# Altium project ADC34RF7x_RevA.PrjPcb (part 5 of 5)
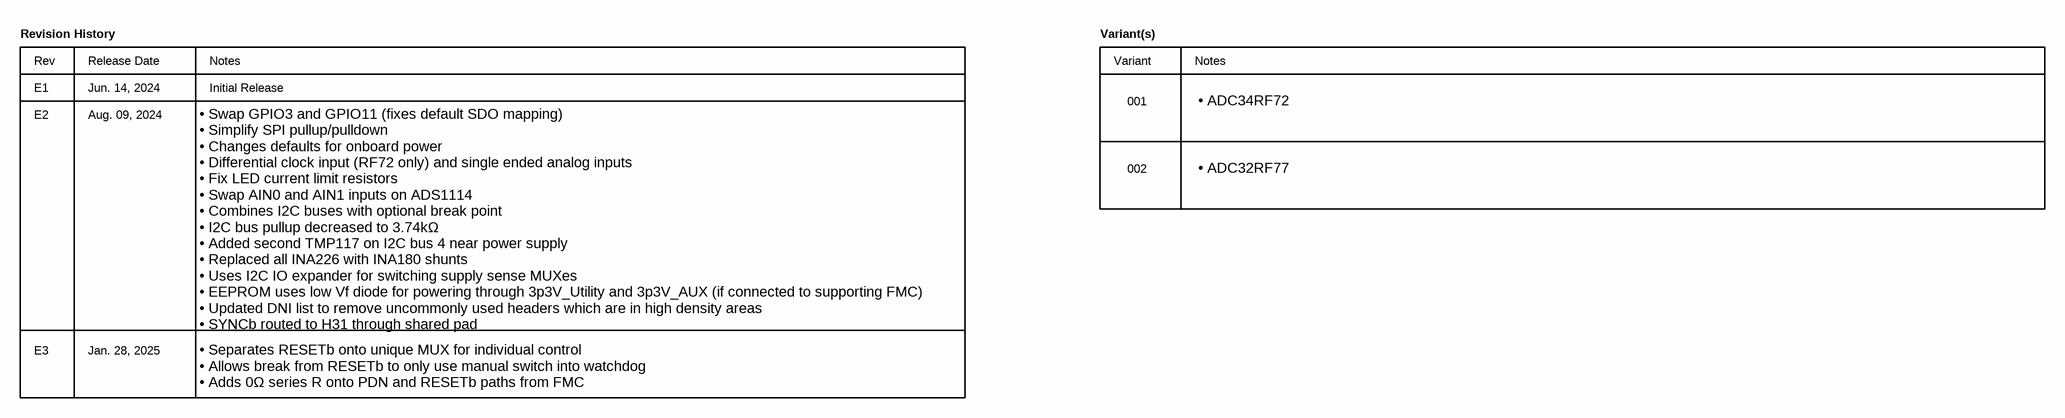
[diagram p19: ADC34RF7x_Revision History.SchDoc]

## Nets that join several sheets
2p3V: ADC34RF7x_Power2_RevA (C221.2 C222.2 FB4.2 FB5.2), ADC34RF7x_Power3_RevA (6 pins), ADC34RF7x_Power4_RevA (6 pins)
3p3V_AUX: ADC34RF7x_FMC_RevA (J29.D32), ADC34RF7x_I2C_Shunts_Margining (D6.1)
3p3V_Utility: ADC34RF7x_LMK_RevA (24 pins), ADC34RF7x_USB_RevA (6 pins), ADC34RF7x_LVL_Shft_RevA (16 pins), ADC34RF7x_MUX_RevA (11 pins), ADC34RF7x_SYSREF_FPGA_MUX_RevA (18 pins), ADC34RF7x_Power1_RevA (C204.2 FC1.3), ADC34RF7x_Power2_RevA (5 pins), ADC34RF7x_Power3_RevA (10 pins), ADC34RF7x_Power4_RevA (10 pins), ADC34RF7x_I2C_Shunts_Margining (51 pins)
12V: ADC34RF7x_Power1_RevA (15 pins), ADC34RF7x_Power_Sequencer (R224.2 R225.1 U62.1), ADC34RF7x_Power2_RevA (16 pins)
AVDD12: ADC34RF7x_ADC_Power_RevA (60 pins), ADC34RF7x_Power3_RevA (C230.2 FB2.2 FB6.2)
AVDD12_I2C_SENSE: ADC34RF7x_I2C_Shunts_Margining (U57.7), ADC34RF7x_uFit_Power (R171.2)
AVDD12_IN: ADC34RF7x_Power3_RevA (C229.2 R133.2 U40.9 U40.10), ADC34RF7x_I2C_Shunts_Margining (R106.1 U33.1)
AVDD12_OUT: ADC34RF7x_Power3_RevA (FB6.1 U40.8), ADC34RF7x_I2C_Shunts_Margining (R106.2 U33.3)
AVDD12_SENSE: ADC34RF7x_ADC_Power_RevA (NT2.1), ADC34RF7x_uFit_Power (R42.1 R171.1)
AVDD12_uFit: ADC34RF7x_Power3_RevA (FB2.1), ADC34RF7x_uFit_Power (J43.11 J43.13)
AVDD18: ADC34RF7x_ADC_Dig_RevA (U3.2), ADC34RF7x_ADC_Power_RevA (38 pins), ADC34RF7x_Power4_RevA (C244.2 FB8.2 FB10.2)
AVDD18_I2C_SENSE: ADC34RF7x_I2C_Shunts_Margining (U57.2), ADC34RF7x_uFit_Power (R174.2)
AVDD18_IN: ADC34RF7x_Power4_RevA (C243.2 R145.2 U46.9 U46.10), ADC34RF7x_I2C_Shunts_Margining (R104.1 U31.1)
AVDD18_OUT: ADC34RF7x_Power4_RevA (FB8.1 U46.8), ADC34RF7x_I2C_Shunts_Margining (R104.2 U31.3)
AVDD18_SENSE: ADC34RF7x_ADC_Power_RevA (NT5.1), ADC34RF7x_uFit_Power (R169.1 R174.1)
AVDD18_uFit: ADC34RF7x_Power4_RevA (FB10.1), ADC34RF7x_uFit_Power (J44.1 J44.3)
CLKVDD12: ADC34RF7x_ADC_Power_RevA (6 pins), ADC34RF7x_Power3_RevA (C237.2 FB3.2 FB7.2)
CLKVDD12_I2C_SENSE: ADC34RF7x_I2C_Shunts_Margining (U57.4), ADC34RF7x_uFit_Power (R172.2)
CLKVDD12_IN: ADC34RF7x_Power3_RevA (C236.2 R139.2 U43.9 U43.10), ADC34RF7x_I2C_Shunts_Margining (R105.1 U32.1)
CLKVDD12_OUT: ADC34RF7x_Power3_RevA (FB7.1 U43.8), ADC34RF7x_I2C_Shunts_Margining (R105.2 U32.3)
CLKVDD12_SENSE: ADC34RF7x_ADC_Power_RevA (NT3.1), ADC34RF7x_uFit_Power (R167.1 R172.1)
CLKVDD12_uFit: ADC34RF7x_Power3_RevA (FB3.1), ADC34RF7x_uFit_Power (J44.9)
CLKVDD18: ADC34RF7x_ADC_Power_RevA (5 pins), ADC34RF7x_Power4_RevA (C251.2 FB9.2 FB11.2)
CLKVDD18_I2C_SENSE: ADC34RF7x_I2C_Shunts_Margining (U57.9), ADC34RF7x_uFit_Power (R173.2)
CLKVDD18_IN: ADC34RF7x_Power4_RevA (C250.2 R151.2 U49.9 U49.10), ADC34RF7x_I2C_Shunts_Margining (R107.1 U34.1)
CLKVDD18_OUT: ADC34RF7x_Power4_RevA (FB9.1 U49.8), ADC34RF7x_I2C_Shunts_Margining (R107.2 U34.3)
CLKVDD18_SENSE: ADC34RF7x_ADC_Power_RevA (NT4.1), ADC34RF7x_uFit_Power (R168.1 R173.1)
CLKVDD18_uFit: ADC34RF7x_Power4_RevA (FB11.1), ADC34RF7x_uFit_Power (J44.13)
DVDD09: ADC34RF7x_ADC_Power_RevA (30 pins), ADC34RF7x_Power2_RevA (7 pins), ADC34RF7x_I2C_Shunts_Margining (R103.2 U28.3)
DVDD09_GND_SENSE: ADC34RF7x_ADC_Power_RevA (NT8.1), ADC34RF7x_uFit_Power (R197.1 R198.1)
DVDD09_I2C_GND_SENSE: ADC34RF7x_I2C_Shunts_Margining (U27.5), ADC34RF7x_uFit_Power (R198.2)
DVDD09_I2C_SENSE: ADC34RF7x_I2C_Shunts_Margining (U27.4), ADC34RF7x_uFit_Power (R170.2)
DVDD09_IN: ADC34RF7x_Power2_RevA (16 pins), ADC34RF7x_I2C_Shunts_Margining (R103.1 U28.1)
DVDD09_SENSE: ADC34RF7x_ADC_Power_RevA (NT1.1), ADC34RF7x_uFit_Power (R41.1 R170.1)
DVDD09_uFit: ADC34RF7x_Power2_RevA (NT6.2 NT7.2), ADC34RF7x_uFit_Power (J43.1 J43.3 J43.5 J43.7)
GND: ADC34RF7x_ADC_Input_AB_RevA (30 pins), ADC34RF7x_ADC_Input_CD_RevA (20 pins), ADC34RF7x_LMK_RevA (28 pins), ADC34RF7x_ADC_Dig_RevA (35 pins), ADC34RF7x_ADC_Power_RevA (129 pins), ADC34RF7x_FMC_RevA (162 pins), ADC34RF7x_USB_RevA (26 pins), ADC34RF7x_LVL_Shft_RevA (28 pins), ADC34RF7x_MUX_RevA (22 pins), ADC34RF7x_SYSREF_FPGA_MUX_RevA (36 pins), ADC34RF7x_Power1_RevA (40 pins), ADC34RF7x_Power_Sequencer (7 pins), ADC34RF7x_Power2_RevA (55 pins), ADC34RF7x_Power3_RevA (24 pins), ADC34RF7x_Power4_RevA (24 pins), ADC34RF7x_I2C_Shunts_Margining (42 pins), ADC34RF7x_uFit_Power (16 pins)
GPIOVDD: ADC34RF7x_ADC_Dig_RevA (R46.1 R47.1 R48.1 U4.6), ADC34RF7x_ADC_Power_RevA (J20.1 U1.L5), ADC34RF7x_LVL_Shft_RevA (8 pins), ADC34RF7x_MUX_RevA (U8.2 U8.6)
VADJ: ADC34RF7x_FMC_RevA (J29.E39 J29.F40 J29.G39 J29.H40), ADC34RF7x_LVL_Shft_RevA (R202.1 SW6.3)
ADC_CLK_N: ADC34RF7x_ADC_Input_AB_RevA (C18.2 C19.2), ADC34RF7x_ADC_Dig_RevA (U1.U9)
ADC_CLK_P: ADC34RF7x_ADC_Input_AB_RevA (C22.2 C23.1), ADC34RF7x_ADC_Dig_RevA (U1.U10)
ADC_JESDCLK_CORECLK_N: ADC34RF7x_FMC_RevA (J29.D9), ADC34RF7x_SYSREF_FPGA_MUX_RevA (U54.10)
ADC_JESDCLK_CORECLK_P: ADC34RF7x_FMC_RevA (J29.D8), ADC34RF7x_SYSREF_FPGA_MUX_RevA (U54.9)
ADC_JESDCLK_N: ADC34RF7x_ADC_Dig_RevA (U1.C9), ADC34RF7x_SYSREF_FPGA_MUX_RevA (C262.2)
ADC_JESDCLK_P: ADC34RF7x_ADC_Dig_RevA (U1.D9), ADC34RF7x_SYSREF_FPGA_MUX_RevA (C261.2)
ADC_JESDCLKIN_LMK_N: ADC34RF7x_LMK_RevA (R55.2), ADC34RF7x_SYSREF_FPGA_MUX_RevA (U56.4)
ADC_JESDCLKIN_LMK_P: ADC34RF7x_LMK_RevA (R54.2), ADC34RF7x_SYSREF_FPGA_MUX_RevA (U56.5)
ADC_JESDCLKIN_N: ADC34RF7x_ADC_Dig_RevA (R180.1 U1.P12), ADC34RF7x_SYSREF_FPGA_MUX_RevA (C68.1)
ADC_JESDCLKIN_P: ADC34RF7x_ADC_Dig_RevA (R180.2 U1.N12), ADC34RF7x_SYSREF_FPGA_MUX_RevA (C65.1)
ADC_SYSREF_LMK_N: ADC34RF7x_LMK_RevA (R61.2), ADC34RF7x_SYSREF_FPGA_MUX_RevA (U55.5)
ADC_SYSREF_LMK_P: ADC34RF7x_LMK_RevA (R58.2), ADC34RF7x_SYSREF_FPGA_MUX_RevA (U55.4)
ADC_SYSREF_N: ADC34RF7x_ADC_Dig_RevA (U1.U6), ADC34RF7x_SYSREF_FPGA_MUX_RevA (R204.2)
ADC_SYSREF_P: ADC34RF7x_ADC_Dig_RevA (U1.U7), ADC34RF7x_SYSREF_FPGA_MUX_RevA (R205.2)
ADC_SYSREFOUT_N: ADC34RF7x_ADC_Dig_RevA (U1.L1), ADC34RF7x_SYSREF_FPGA_MUX_RevA (C260.2)
ADC_SYSREFOUT_P: ADC34RF7x_ADC_Dig_RevA (U1.K1), ADC34RF7x_SYSREF_FPGA_MUX_RevA (C259.2)
CSb_LMK: ADC34RF7x_LMK_RevA (U2.18), ADC34RF7x_MUX_RevA (J21.5 U6.5)
CSb_LMK_FMC_3p3V: ADC34RF7x_LVL_Shft_RevA (U15.11), ADC34RF7x_MUX_RevA (U6.4)
CSb_LMK_FMC_VADJ: ADC34RF7x_FMC_RevA (J29.G16), ADC34RF7x_LVL_Shft_RevA (U15.2 U17.1)
CSb_LMK_USB: ADC34RF7x_USB_RevA (J28.29), ADC34RF7x_MUX_RevA (U6.3)
DCLKA_N: ADC34RF7x_ADC_Dig_RevA (U1.F17), ADC34RF7x_FMC_RevA (J29.D21)
DCLKA_P: ADC34RF7x_ADC_Dig_RevA (U1.E17), ADC34RF7x_FMC_RevA (J29.D20)
DCLKB_N: ADC34RF7x_ADC_Dig_RevA (U1.F1), ADC34RF7x_FMC_RevA (J29.F4)
DCLKB_P: ADC34RF7x_ADC_Dig_RevA (U1.E1), ADC34RF7x_FMC_RevA (J29.F5)
DOUT0_FMC_N: ADC34RF7x_ADC_Dig_RevA (C77.2), ADC34RF7x_FMC_RevA (J29.A18)
DOUT0_FMC_P: ADC34RF7x_ADC_Dig_RevA (C76.2), ADC34RF7x_FMC_RevA (J29.A19)
DOUT1_FMC_N: ADC34RF7x_ADC_Dig_RevA (C79.2), ADC34RF7x_FMC_RevA (J29.B16)
DOUT1_FMC_P: ADC34RF7x_ADC_Dig_RevA (C78.2), ADC34RF7x_FMC_RevA (J29.B17)
DOUT2_FMC_N: ADC34RF7x_ADC_Dig_RevA (C81.2), ADC34RF7x_FMC_RevA (J29.A14)
DOUT2_FMC_P: ADC34RF7x_ADC_Dig_RevA (C80.2), ADC34RF7x_FMC_RevA (J29.A15)
DOUT3_FMC_N: ADC34RF7x_ADC_Dig_RevA (C83.2), ADC34RF7x_FMC_RevA (J29.B12)
DOUT3_FMC_P: ADC34RF7x_ADC_Dig_RevA (C82.2), ADC34RF7x_FMC_RevA (J29.B13)
DOUT4_FMC_N: ADC34RF7x_ADC_Dig_RevA (C85.2), ADC34RF7x_FMC_RevA (J29.A2)
DOUT4_FMC_P: ADC34RF7x_ADC_Dig_RevA (C84.2), ADC34RF7x_FMC_RevA (J29.A3)
DOUT5_FMC_N: ADC34RF7x_ADC_Dig_RevA (C87.2), ADC34RF7x_FMC_RevA (J29.C6)
DOUT5_FMC_P: ADC34RF7x_ADC_Dig_RevA (C86.2), ADC34RF7x_FMC_RevA (J29.C7)
DOUT6_FMC_N: ADC34RF7x_ADC_Dig_RevA (C89.2), ADC34RF7x_FMC_RevA (J29.A6)
DOUT6_FMC_P: ADC34RF7x_ADC_Dig_RevA (C88.2), ADC34RF7x_FMC_RevA (J29.A7)
DOUT7_FMC_N: ADC34RF7x_ADC_Dig_RevA (C91.2), ADC34RF7x_FMC_RevA (J29.A10)
DOUT7_FMC_P: ADC34RF7x_ADC_Dig_RevA (C90.2), ADC34RF7x_FMC_RevA (J29.A11)
FCLKA_N: ADC34RF7x_ADC_Dig_RevA (U1.H17), ADC34RF7x_FMC_RevA (J29.G3)
FCLKA_P: ADC34RF7x_ADC_Dig_RevA (U1.G17), ADC34RF7x_FMC_RevA (J29.G2)
FCLKB_N: ADC34RF7x_ADC_Dig_RevA (U1.H1), ADC34RF7x_FMC_RevA (J29.E2)
FCLKB_P: ADC34RF7x_ADC_Dig_RevA (U1.G1), ADC34RF7x_FMC_RevA (J29.E3)
FMC_GA0: ADC34RF7x_FMC_RevA (J29.C34), ADC34RF7x_I2C_Shunts_Margining (R212.1 U13.1)
FMC_GA1: ADC34RF7x_FMC_RevA (J29.D35), ADC34RF7x_I2C_Shunts_Margining (R213.1 U13.2)
FPGA_SYSREF_LMK_N: ADC34RF7x_LMK_RevA (R181.2), ADC34RF7x_SYSREF_FPGA_MUX_RevA (C101.2)
FPGA_SYSREF_LMK_P: ADC34RF7x_LMK_RevA (R166.2), ADC34RF7x_SYSREF_FPGA_MUX_RevA (C100.2)
FPGA_SYSREF_N: ADC34RF7x_FMC_RevA (J29.G10), ADC34RF7x_SYSREF_FPGA_MUX_RevA (U53.12)
FPGA_SYSREF_P: ADC34RF7x_FMC_RevA (J29.G9), ADC34RF7x_SYSREF_FPGA_MUX_RevA (U53.11)
GPIO0_ADC: ADC34RF7x_ADC_Dig_RevA (J13.1 U1.J4), ADC34RF7x_MUX_RevA (U10.12)
GPIO1_ADC: ADC34RF7x_ADC_Dig_RevA (J13.3 U1.K4), ADC34RF7x_MUX_RevA (U10.1)
GPIO2_ADC: ADC34RF7x_ADC_Dig_RevA (J13.5 U1.L14), ADC34RF7x_MUX_RevA (U10.14)
GPIO3_ADC: ADC34RF7x_ADC_Dig_RevA (J13.7 U1.J15), ADC34RF7x_MUX_RevA (U10.5)
GPIO8_ADC: ADC34RF7x_ADC_Dig_RevA (J41.1 U1.L4), ADC34RF7x_MUX_RevA (U10.15)
GPIO9_ADC: ADC34RF7x_ADC_Dig_RevA (J41.3 U1.J3), ADC34RF7x_MUX_RevA (U10.11)
GPIO10_ADC: ADC34RF7x_ADC_Dig_RevA (J41.5 U1.K3), ADC34RF7x_MUX_RevA (U10.2)
GPIO13_ADC: ADC34RF7x_ADC_Dig_RevA (J41.11 U1.K2), ADC34RF7x_MUX_RevA (U10.4)
GPIO14_ADC: ADC34RF7x_ADC_Dig_RevA (J41.13 U1.L2), ADC34RF7x_LVL_Shft_RevA (U24.10)
GPIO14_FPGA: ADC34RF7x_FMC_RevA (J29.H19), ADC34RF7x_LVL_Shft_RevA (U24.3)
GPIO15_ADC: ADC34RF7x_ADC_Dig_RevA (J41.15 U1.C2), ADC34RF7x_LVL_Shft_RevA (U24.9)
GPIO15_FPGA: ADC34RF7x_FMC_RevA (J29.H20), ADC34RF7x_LVL_Shft_RevA (U24.4)
GPIO16_ADC: ADC34RF7x_ADC_Dig_RevA (J42.1 U1.D2), ADC34RF7x_LVL_Shft_RevA (U22.12)
GPIO16_FPGA: ADC34RF7x_FMC_RevA (J29.J18), ADC34RF7x_LVL_Shft_RevA (U22.1)
GPIO17_ADC: ADC34RF7x_ADC_Dig_RevA (J42.3 U1.K16), ADC34RF7x_LVL_Shft_RevA (U22.11)
GPIO17_FPGA: ADC34RF7x_FMC_RevA (J29.J19), ADC34RF7x_LVL_Shft_RevA (U22.2)
GPIO18_ADC: ADC34RF7x_ADC_Dig_RevA (J42.5 U1.L16), ADC34RF7x_LVL_Shft_RevA (U22.10)
GPIO18_FPGA: ADC34RF7x_FMC_RevA (J29.J21), ADC34RF7x_LVL_Shft_RevA (U22.3)
GPIO19_ADC: ADC34RF7x_ADC_Dig_RevA (J42.7 U1.J17), ADC34RF7x_LVL_Shft_RevA (U22.9)
GPIO19_FPGA: ADC34RF7x_FMC_RevA (J29.J22), ADC34RF7x_LVL_Shft_RevA (U22.4)
GPIO20_ADC: ADC34RF7x_ADC_Dig_RevA (J42.9 U1.K17), ADC34RF7x_LVL_Shft_RevA (U25.12)
GPIO20_FPGA: ADC34RF7x_FMC_RevA (J29.K19), ADC34RF7x_LVL_Shft_RevA (U25.1)
GPIO21_ADC: ADC34RF7x_ADC_Dig_RevA (J42.11 U1.L17), ADC34RF7x_LVL_Shft_RevA (U25.11)
GPIO21_FPGA: ADC34RF7x_FMC_RevA (J29.K20), ADC34RF7x_LVL_Shft_RevA (U25.2)
GPIO22_ADC: ADC34RF7x_ADC_Dig_RevA (J42.13 U1.C16), ADC34RF7x_LVL_Shft_RevA (U25.10)
GPIO22_FPGA: ADC34RF7x_FMC_RevA (J29.K22), ADC34RF7x_LVL_Shft_RevA (U25.3)
GPIO23_ADC: ADC34RF7x_ADC_Dig_RevA (J42.15 U1.D16), ADC34RF7x_LVL_Shft_RevA (U25.9)
GPIO23_FPGA: ADC34RF7x_FMC_RevA (J29.K23), ADC34RF7x_LVL_Shft_RevA (U25.4)
GPIO_MUX0_FT: ADC34RF7x_USB_RevA (J28.9), ADC34RF7x_LVL_Shft_RevA (U19.3)
GPIO_MUX1_FT: ADC34RF7x_USB_RevA (J28.11), ADC34RF7x_LVL_Shft_RevA (U19.4)
GPIO_MUX_0_FMC_GPIOVDD: ADC34RF7x_LVL_Shft_RevA (U24.12), ADC34RF7x_MUX_RevA (U11.1)
GPIO_MUX_0_FPGA: ADC34RF7x_FMC_RevA (R200.1 R201.2), ADC34RF7x_LVL_Shft_RevA (U24.1)
GPIO_MUX_0_USB_GPIOVDD: ADC34RF7x_LVL_Shft_RevA (U19.10), ADC34RF7x_MUX_RevA (U11.16)
GPIO_MUX_1_FMC_GPIOVDD: ADC34RF7x_LVL_Shft_RevA (U24.11), ADC34RF7x_MUX_RevA (U11.4)
GPIO_MUX_1_FPGA: ADC34RF7x_FMC_RevA (J29.H17), ADC34RF7x_LVL_Shft_RevA (U24.2)
GPIO_MUX_1_USB_GPIOVDD: ADC34RF7x_LVL_Shft_RevA (U19.9), ADC34RF7x_MUX_RevA (U11.3)
INA_ADC_N: ADC34RF7x_ADC_Input_AB_RevA (R2.2 R4.2), ADC34RF7x_ADC_Dig_RevA (U1.R17)
INA_ADC_P: ADC34RF7x_ADC_Input_AB_RevA (R4.1 R7.2), ADC34RF7x_ADC_Dig_RevA (U1.P17)
INB_ADC_N: ADC34RF7x_ADC_Input_AB_RevA (R9.2 R11.2), ADC34RF7x_ADC_Dig_RevA (U1.U14)
INB_ADC_P: ADC34RF7x_ADC_Input_AB_RevA (R11.1 R14.2), ADC34RF7x_ADC_Dig_RevA (U1.U15)
INC_ADC_N: ADC34RF7x_ADC_Input_CD_RevA (R20.2 R22.2), ADC34RF7x_ADC_Dig_RevA (U1.P1)
INC_ADC_P: ADC34RF7x_ADC_Input_CD_RevA (R22.1 R25.2), ADC34RF7x_ADC_Dig_RevA (U1.R1)
IND_ADC_N: ADC34RF7x_ADC_Input_CD_RevA (R27.2 R29.2), ADC34RF7x_ADC_Dig_RevA (U1.U3)
IND_ADC_P: ADC34RF7x_ADC_Input_CD_RevA (R29.1 R32.2), ADC34RF7x_ADC_Dig_RevA (U1.U4)
LMK_CLK: ADC34RF7x_ADC_Input_AB_RevA (R18.1), ADC34RF7x_LMK_RevA (C55.1)
LMK_CORECLK_N: ADC34RF7x_LMK_RevA (R81.2), ADC34RF7x_FMC_RevA (J29.G7)
LMK_CORECLK_P: ADC34RF7x_LMK_RevA (R80.2), ADC34RF7x_FMC_RevA (J29.G6)
LVDSA0_N: ADC34RF7x_ADC_Dig_RevA (U1.G11), ADC34RF7x_FMC_RevA (J29.C23)
LVDSA0_P: ADC34RF7x_ADC_Dig_RevA (U1.H11), ADC34RF7x_FMC_RevA (J29.C22)
LVDSA1_N: ADC34RF7x_ADC_Dig_RevA (U1.E11), ADC34RF7x_FMC_RevA (J29.D24)
LVDSA1_P: ADC34RF7x_ADC_Dig_RevA (U1.F11), ADC34RF7x_FMC_RevA (J29.D23)
LVDSA2_N: ADC34RF7x_ADC_Dig_RevA (U1.C11), ADC34RF7x_FMC_RevA (J29.G22)
LVDSA2_P: ADC34RF7x_ADC_Dig_RevA (U1.D11), ADC34RF7x_FMC_RevA (J29.G21)
LVDSA3_N: ADC34RF7x_ADC_Dig_RevA (U1.G12), ADC34RF7x_FMC_RevA (J29.H23)
LVDSA3_P: ADC34RF7x_ADC_Dig_RevA (U1.H12), ADC34RF7x_FMC_RevA (J29.H22)
LVDSA4_N: ADC34RF7x_ADC_Dig_RevA (U1.E12), ADC34RF7x_FMC_RevA (J29.D27)
LVDSA4_P: ADC34RF7x_ADC_Dig_RevA (U1.F12), ADC34RF7x_FMC_RevA (J29.D26)
LVDSA5_N: ADC34RF7x_ADC_Dig_RevA (U1.C12), ADC34RF7x_FMC_RevA (J29.C27)
LVDSA5_P: ADC34RF7x_ADC_Dig_RevA (U1.D12), ADC34RF7x_FMC_RevA (J29.C26)
LVDSA6_N: ADC34RF7x_ADC_Dig_RevA (U1.E13), ADC34RF7x_FMC_RevA (J29.H25)
LVDSA6_P: ADC34RF7x_ADC_Dig_RevA (U1.F13), ADC34RF7x_FMC_RevA (J29.H26)
LVDSA7_N: ADC34RF7x_ADC_Dig_RevA (U1.C13), ADC34RF7x_FMC_RevA (J29.G25)
LVDSA7_P: ADC34RF7x_ADC_Dig_RevA (U1.D13), ADC34RF7x_FMC_RevA (J29.G24)
LVDSA8_N: ADC34RF7x_ADC_Dig_RevA (U1.G14), ADC34RF7x_FMC_RevA (J29.H37)
LVDSA8_P: ADC34RF7x_ADC_Dig_RevA (U1.H14), ADC34RF7x_FMC_RevA (J29.H38)
LVDSA9_N: ADC34RF7x_ADC_Dig_RevA (U1.E14), ADC34RF7x_FMC_RevA (J29.H29)
LVDSA9_P: ADC34RF7x_ADC_Dig_RevA (U1.F14), ADC34RF7x_FMC_RevA (J29.H28)
LVDSA10_N: ADC34RF7x_ADC_Dig_RevA (U1.C14), ADC34RF7x_FMC_RevA (J29.G28)
LVDSA10_P: ADC34RF7x_ADC_Dig_RevA (U1.D14), ADC34RF7x_FMC_RevA (J29.G27)
LVDSA11_N: ADC34RF7x_ADC_Dig_RevA (U1.G15), ADC34RF7x_FMC_RevA (J29.G36)
LVDSA11_P: ADC34RF7x_ADC_Dig_RevA (U1.H15), ADC34RF7x_FMC_RevA (J29.G37)
LVDSA12_N: ADC34RF7x_ADC_Dig_RevA (U1.E15), ADC34RF7x_FMC_RevA (R183.2)
LVDSA12_P: ADC34RF7x_ADC_Dig_RevA (U1.F15), ADC34RF7x_FMC_RevA (R184.2)
LVDSA13_N: ADC34RF7x_ADC_Dig_RevA (U1.C15), ADC34RF7x_FMC_RevA (J29.G30)
LVDSA13_P: ADC34RF7x_ADC_Dig_RevA (U1.D15), ADC34RF7x_FMC_RevA (J29.G31)
LVDSA14_N: ADC34RF7x_ADC_Dig_RevA (U1.G16), ADC34RF7x_FMC_RevA (J29.H34)
LVDSA14_P: ADC34RF7x_ADC_Dig_RevA (U1.H16), ADC34RF7x_FMC_RevA (J29.H35)
LVDSA15_N: ADC34RF7x_ADC_Dig_RevA (U1.E16), ADC34RF7x_FMC_RevA (J29.G33)
LVDSA15_P: ADC34RF7x_ADC_Dig_RevA (U1.F16), ADC34RF7x_FMC_RevA (J29.G34)
LVDSB0_N: ADC34RF7x_ADC_Dig_RevA (U1.G7), ADC34RF7x_FMC_RevA (J29.E13)
LVDSB0_P: ADC34RF7x_ADC_Dig_RevA (U1.H7), ADC34RF7x_FMC_RevA (J29.E12)
LVDSB1_N: ADC34RF7x_ADC_Dig_RevA (U1.E7), ADC34RF7x_FMC_RevA (J29.K16)
LVDSB1_P: ADC34RF7x_ADC_Dig_RevA (U1.F7), ADC34RF7x_FMC_RevA (J29.K17)
LVDSB2_N: ADC34RF7x_ADC_Dig_RevA (U1.C7), ADC34RF7x_FMC_RevA (J29.F16)
LVDSB2_P: ADC34RF7x_ADC_Dig_RevA (U1.D7), ADC34RF7x_FMC_RevA (J29.F17)
LVDSB3_N: ADC34RF7x_ADC_Dig_RevA (U1.G6), ADC34RF7x_FMC_RevA (J29.E7)
LVDSB3_P: ADC34RF7x_ADC_Dig_RevA (U1.H6), ADC34RF7x_FMC_RevA (J29.E6)
LVDSB4_N: ADC34RF7x_ADC_Dig_RevA (U1.E6), ADC34RF7x_FMC_RevA (J29.E10)
LVDSB4_P: ADC34RF7x_ADC_Dig_RevA (U1.F6), ADC34RF7x_FMC_RevA (J29.E9)
LVDSB5_N: ADC34RF7x_ADC_Dig_RevA (U1.C6), ADC34RF7x_FMC_RevA (J29.E16)
LVDSB5_P: ADC34RF7x_ADC_Dig_RevA (U1.D6), ADC34RF7x_FMC_RevA (J29.E15)
LVDSB6_N: ADC34RF7x_ADC_Dig_RevA (U1.E5), ADC34RF7x_FMC_RevA (J29.J16)
LVDSB6_P: ADC34RF7x_ADC_Dig_RevA (U1.F5), ADC34RF7x_FMC_RevA (J29.J15)
LVDSB7_N: ADC34RF7x_ADC_Dig_RevA (U1.C5), ADC34RF7x_FMC_RevA (J29.K11)
LVDSB7_P: ADC34RF7x_ADC_Dig_RevA (U1.D5), ADC34RF7x_FMC_RevA (J29.K10)
LVDSB8_N: ADC34RF7x_ADC_Dig_RevA (U1.G4), ADC34RF7x_FMC_RevA (J29.F11)
LVDSB8_P: ADC34RF7x_ADC_Dig_RevA (U1.H4), ADC34RF7x_FMC_RevA (J29.F10)
LVDSB9_N: ADC34RF7x_ADC_Dig_RevA (U1.E4), ADC34RF7x_FMC_RevA (J29.F8)
LVDSB9_P: ADC34RF7x_ADC_Dig_RevA (U1.F4), ADC34RF7x_FMC_RevA (J29.F7)
LVDSB10_N: ADC34RF7x_ADC_Dig_RevA (U1.C4), ADC34RF7x_FMC_RevA (J29.F14)
LVDSB10_P: ADC34RF7x_ADC_Dig_RevA (U1.D4), ADC34RF7x_FMC_RevA (J29.F13)
LVDSB11_N: ADC34RF7x_ADC_Dig_RevA (U1.G3), ADC34RF7x_FMC_RevA (J29.K8)
LVDSB11_P: ADC34RF7x_ADC_Dig_RevA (U1.H3), ADC34RF7x_FMC_RevA (J29.K7)
LVDSB12_N: ADC34RF7x_ADC_Dig_RevA (U1.E3), ADC34RF7x_FMC_RevA (J29.K14)
LVDSB12_P: ADC34RF7x_ADC_Dig_RevA (U1.F3), ADC34RF7x_FMC_RevA (J29.K13)
LVDSB13_N: ADC34RF7x_ADC_Dig_RevA (U1.C3), ADC34RF7x_FMC_RevA (J29.J10)
LVDSB13_P: ADC34RF7x_ADC_Dig_RevA (U1.D3), ADC34RF7x_FMC_RevA (J29.J9)
LVDSB14_N: ADC34RF7x_ADC_Dig_RevA (U1.G2), ADC34RF7x_FMC_RevA (J29.J7)
LVDSB14_P: ADC34RF7x_ADC_Dig_RevA (U1.H2), ADC34RF7x_FMC_RevA (J29.J6)
LVDSB15_N: ADC34RF7x_ADC_Dig_RevA (U1.E2), ADC34RF7x_FMC_RevA (J29.J12)
LVDSB15_P: ADC34RF7x_ADC_Dig_RevA (U1.F2), ADC34RF7x_FMC_RevA (J29.J13)
MGTREFCLK0_FMC_N: ADC34RF7x_FMC_RevA (J29.D5), ADC34RF7x_SYSREF_FPGA_MUX_RevA (C64.1)
MGTREFCLK0_FMC_P: ADC34RF7x_FMC_RevA (J29.D4), ADC34RF7x_SYSREF_FPGA_MUX_RevA (C59.1)
MGTREFCLK0_LMK_N: ADC34RF7x_LMK_RevA (R63.2), ADC34RF7x_SYSREF_FPGA_MUX_RevA (U52.4)
MGTREFCLK0_LMK_P: ADC34RF7x_LMK_RevA (R62.2), ADC34RF7x_SYSREF_FPGA_MUX_RevA (U52.5)
MGTREFCLK1_FMC_N: ADC34RF7x_LMK_RevA (C67.2), ADC34RF7x_FMC_RevA (J29.B21)
MGTREFCLK1_FMC_P: ADC34RF7x_LMK_RevA (C66.2), ADC34RF7x_FMC_RevA (J29.B20)
PDN_ADC_FMC_GPIOVDD: ADC34RF7x_LVL_Shft_RevA (U21.6), ADC34RF7x_MUX_RevA (U11.11)
PDN_ADC_FMC_VADJ: ADC34RF7x_FMC_RevA (R218.1), ADC34RF7x_LVL_Shft_RevA (R238.1 U21.3)
PDN_ADC_FT: ADC34RF7x_USB_RevA (J28.5), ADC34RF7x_LVL_Shft_RevA (U19.2)
PDN_ADC_GPIOVDD: ADC34RF7x_ADC_Dig_RevA (J41.9 R50.1 U1.J2), ADC34RF7x_MUX_RevA (U11.10)
PDN_ADC_USB_GPIOVDD: ADC34RF7x_LVL_Shft_RevA (U19.11), ADC34RF7x_MUX_RevA (U11.12)
PG-3p3V_Util: ADC34RF7x_Power1_RevA (R112.1 U36.19), ADC34RF7x_Power2_RevA (R228.1 U64.2)
PG-M2C: ADC34RF7x_FMC_RevA (D2.1 R199.1), ADC34RF7x_Power4_RevA (R233.2)
PG-switcher: ADC34RF7x_Power2_RevA (R125.2 U39.3), ADC34RF7x_Power3_RevA (R232.1 U66.2)
PG-VDD12: ADC34RF7x_Power3_RevA (R229.2), ADC34RF7x_Power4_RevA (R235.1 U68.1)
RSTb_ADC_FMC_GPIOVDD: ADC34RF7x_LVL_Shft_RevA (U21.7), ADC34RF7x_MUX_RevA (U61.4)
RSTb_ADC_FMC_VADJ: ADC34RF7x_FMC_RevA (R217.1), ADC34RF7x_LVL_Shft_RevA (R237.1 U21.2)
RSTb_ADC_FT: ADC34RF7x_USB_RevA (J28.3), ADC34RF7x_LVL_Shft_RevA (U19.1)
RSTb_ADC_GPIOVDD: ADC34RF7x_ADC_Dig_RevA (R219.1), ADC34RF7x_MUX_RevA (U61.1)
RSTb_ADC_USB_GPIOVDD: ADC34RF7x_LVL_Shft_RevA (U19.12), ADC34RF7x_MUX_RevA (U61.5)
SCL: ADC34RF7x_USB_RevA (R66.1 R68.1 R69.1 TP6.1), ADC34RF7x_I2C_Shunts_Margining (6 pins)
SCL0: ADC34RF7x_Power3_RevA (U44.3 U45.3), ADC34RF7x_I2C_Shunts_Margining (R93.1 U26.2)
SCL1: ADC34RF7x_Power4_RevA (U50.3 U51.3), ADC34RF7x_I2C_Shunts_Margining (R95.1 U26.4)
SCL2: ADC34RF7x_Power2_RevA (U38.3), ADC34RF7x_I2C_Shunts_Margining (R97.1 U26.6)
SCL3: ADC34RF7x_Power4_RevA (U47.3 U48.3), ADC34RF7x_I2C_Shunts_Margining (R99.1 U26.8)
SCL4: ADC34RF7x_Power3_RevA (U41.3 U42.3), ADC34RF7x_I2C_Shunts_Margining (R101.1 U26.11 U60.A2)
SCL_FMC: ADC34RF7x_FMC_RevA (J29.C30), ADC34RF7x_LVL_Shft_RevA (U9.6)
SCL_FMC_3p3V: ADC34RF7x_USB_RevA (R69.2), ADC34RF7x_LVL_Shft_RevA (U9.3)
SCLK_ADC: ADC34RF7x_ADC_Dig_RevA (J13.11 U1.K15), ADC34RF7x_MUX_RevA (R59.2)
SCLK_ADC_FMC_GPIOVDD: ADC34RF7x_LVL_Shft_RevA (U18.12), ADC34RF7x_MUX_RevA (U7.1)
SCLK_ADC_FT: ADC34RF7x_USB_RevA (J28.4), ADC34RF7x_LVL_Shft_RevA (U23.1)
SCLK_ADC_USB_GPIOVDD: ADC34RF7x_LVL_Shft_RevA (U23.12), ADC34RF7x_MUX_RevA (U7.16)
SCLK_FMC_VADJ: ADC34RF7x_FMC_RevA (J29.G12), ADC34RF7x_LVL_Shft_RevA (U15.1 U18.1)
SCLK_FPGA_FT: ADC34RF7x_USB_RevA (J28.40), ADC34RF7x_LVL_Shft_RevA (U16.1)
SCLK_FPGA_VADJ: ADC34RF7x_FMC_RevA (J29.C10), ADC34RF7x_LVL_Shft_RevA (U16.12)
SCLK_LMK: ADC34RF7x_LMK_RevA (U2.19), ADC34RF7x_MUX_RevA (R53.1)
SCLK_LMK_FMC_3p3V: ADC34RF7x_LVL_Shft_RevA (U15.12), ADC34RF7x_MUX_RevA (U6.1)
SCLK_LMK_USB: ADC34RF7x_USB_RevA (J28.33), ADC34RF7x_MUX_RevA (U6.16)
SDA: ADC34RF7x_USB_RevA (R67.1 R185.1 R186.1 TP7.1), ADC34RF7x_I2C_Shunts_Margining (6 pins)
SDA0: ADC34RF7x_Power3_RevA (U44.4 U45.4), ADC34RF7x_I2C_Shunts_Margining (R92.1 U26.1)
SDA1: ADC34RF7x_Power4_RevA (U50.4 U51.4), ADC34RF7x_I2C_Shunts_Margining (R94.1 U26.3)
SDA2: ADC34RF7x_Power2_RevA (U38.4), ADC34RF7x_I2C_Shunts_Margining (R96.1 U26.5)
SDA3: ADC34RF7x_Power4_RevA (U47.4 U48.4), ADC34RF7x_I2C_Shunts_Margining (R98.1 U26.7)
SDA4: ADC34RF7x_Power3_RevA (U41.4 U42.4), ADC34RF7x_I2C_Shunts_Margining (R100.1 U26.10 U60.A1)
SDA_FMC: ADC34RF7x_FMC_RevA (J29.C31), ADC34RF7x_LVL_Shft_RevA (U9.7)
SDA_FMC_3p3V: ADC34RF7x_USB_RevA (R186.2), ADC34RF7x_LVL_Shft_RevA (U9.2)
SDI_FMC_VADJ: ADC34RF7x_FMC_RevA (J29.G13), ADC34RF7x_LVL_Shft_RevA (U15.3 U18.3)
SDI_LMK_USB: ADC34RF7x_USB_RevA (J28.35), ADC34RF7x_MUX_RevA (U6.9)
SDIOr_ADC: ADC34RF7x_ADC_Dig_RevA (J41.7 U1.L3), ADC34RF7x_MUX_RevA (J22.4 J23.2 R60.2)
SDIOr_ADC_FMC_GPIOVDD: ADC34RF7x_LVL_Shft_RevA (U18.9), ADC34RF7x_MUX_RevA (U7.11)
SDIOr_ADC_FT: ADC34RF7x_USB_RevA (J28.10), ADC34RF7x_LVL_Shft_RevA (U23.3)
SDIOr_ADC_USB_GPIOVDD: ADC34RF7x_LVL_Shft_RevA (U23.10), ADC34RF7x_MUX_RevA (U7.12)
SDIOr_FPGA_FT: ADC34RF7x_USB_RevA (J28.46), ADC34RF7x_LVL_Shft_RevA (U16.3)
SDIOr_FPGA_VADJ: ADC34RF7x_FMC_RevA (J29.C14), ADC34RF7x_LVL_Shft_RevA (U16.10)
SDIOr_LMK: ADC34RF7x_LMK_RevA (U2.5), ADC34RF7x_MUX_RevA (J21.4 R56.2 U6.10)
SDIOr_LMK_FMC_3p3V: ADC34RF7x_LVL_Shft_RevA (U15.9), ADC34RF7x_MUX_RevA (U6.11)
SDIOw_ADC: ADC34RF7x_ADC_Dig_RevA (J13.13 U1.L15), ADC34RF7x_MUX_RevA (J23.3 R187.2)
SDIOw_ADC_FMC_GPIOVDD: ADC34RF7x_LVL_Shft_RevA (U18.10), ADC34RF7x_MUX_RevA (U7.4)
SDIOw_ADC_FT: ADC34RF7x_USB_RevA (J28.6), ADC34RF7x_LVL_Shft_RevA (U23.2)
SDIOw_ADC_USB_GPIOVDD: ADC34RF7x_LVL_Shft_RevA (U23.11), ADC34RF7x_MUX_RevA (U7.3)
SDIOw_FPGA_FT: ADC34RF7x_USB_RevA (J28.42), ADC34RF7x_LVL_Shft_RevA (U16.2)
SDIOw_FPGA_VADJ: ADC34RF7x_FMC_RevA (J29.C11), ADC34RF7x_LVL_Shft_RevA (U16.11)
SDIOw_LMK: ADC34RF7x_LMK_RevA (U2.20), ADC34RF7x_MUX_RevA (J21.3 U6.7)
SDIOw_LMK_FMC_3p3V: ADC34RF7x_LVL_Shft_RevA (U15.10), ADC34RF7x_MUX_RevA (U6.8)
SDO_FMC_VADJ: ADC34RF7x_FMC_RevA (J29.G15), ADC34RF7x_LVL_Shft_RevA (U17.4 U20.4)
SDO_LMK_USB: ADC34RF7x_USB_RevA (J28.27), ADC34RF7x_MUX_RevA (U6.12)
SEN_ADC: ADC34RF7x_ADC_Dig_RevA (J13.15 U1.J16), ADC34RF7x_MUX_RevA (J22.5 U7.7)
SEN_ADC_FMC_GPIOVDD: ADC34RF7x_LVL_Shft_RevA (U18.11), ADC34RF7x_MUX_RevA (U7.8)
SEN_ADC_FMC_VADJ: ADC34RF7x_FMC_RevA (J29.G18), ADC34RF7x_LVL_Shft_RevA (U18.2 U20.1)
SEN_ADC_FT: ADC34RF7x_USB_RevA (J28.12), ADC34RF7x_LVL_Shft_RevA (U23.4)
SEN_ADC_USB_GPIOVDD: ADC34RF7x_LVL_Shft_RevA (U23.9), ADC34RF7x_MUX_RevA (U7.9)
SEN_FPGA_FT: ADC34RF7x_USB_RevA (J28.48), ADC34RF7x_LVL_Shft_RevA (U16.4)
SEN_FPGA_VADJ: ADC34RF7x_FMC_RevA (J29.C15), ADC34RF7x_LVL_Shft_RevA (U16.9)
SEQ_DVDD_09: ADC34RF7x_Power_Sequencer (U63.6), ADC34RF7x_Power2_RevA (R227.1 U64.1)
SEQ_VDD_12: ADC34RF7x_Power_Sequencer (U63.5), ADC34RF7x_Power3_RevA (R231.1 U66.1)
SEQ_VDD_18: ADC34RF7x_Power_Sequencer (U63.4), ADC34RF7x_Power4_RevA (R236.1 U68.2)

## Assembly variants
001-ADC34RF72: not fitted C1 C2 C7 C9 C10 C15 C17 C18 C23 C25 C27 C31 C33 C34 C39 C55 C188 C189 F1 FB2 FB3 FB10 FB11 J13 J21 J22 J41 J42 J43 J44 R4 R11 R17 R18 R22 R29 R34 R35 R36 R38 R39 R41 R42 R45 R52 R58 R61 R62 R63 R64 R69 R70 R83 R115 R167 R168 R169 R175 R176 R180 R183 R186 R187 R188 R189 R190 R193 R194 R197 R199 R200 R202 R221 R222 R227 R228 R231 R232 R235 R236 TP11 TP12; alternate parts T2 -> cmp00062, T1 -> cmp00062, T4 -> cmp00062, T5 -> cmp00062
002-ADC34RF75: not fitted C1 C2 C7 C9 C10 C15 C17 C18 C23 C25 C27 C31 C33 C34 C39 C55 C188 C189 F1 FB2 FB3 FB10 FB11 J13 J21 J22 J41 J42 J43 J44 R4 R11 R17 R18 R22 R29 R34 R35 R36 R38 R39 R41 R42 R45 R52 R58 R61 R62 R63 R64 R69 R70 R83 R115 R167 R168 R169 R175 R176 R180 R183 R186 R187 R188 R189 R190 R193 R194 R197 R199 R200 R202 R220 R222 R227 R228 R231 R232 R235 R236 TP11 TP12; alternate parts T2 -> cmp00062, T1 -> cmp00062, T4 -> cmp00062, T5 -> cmp00062, U1 -> ADC34RF75ANH
003-ADC32RF77: not fitted C1 C2 C7 C9 C10 C11 C12 C13 C14 C15 C16 C17 C18 C23 C25 C27 C31 C33 C34 C35 C36 C37 C38 C39 C40 C55 C188 C189 F1 FB2 FB3 FB10 FB11 J3 J4 J9 J10 J13 J21 J22 J41 J42 J43 J44 R4 R8 R9 R10 R11 R12 R13 R14 R17 R18 R22 R26 R27 R28 R29 R30 R31 R32 R34 R35 R36 R38 R39 R41 R42 R45 R52 R58 R61 R62 R63 R64 R69 R70 R83 R115 R167 R168 R169 R175 R176 R180 R183 R186 R187 R188 R189 R190 R193 R194 R197 R199 R200 R202 R220 R221 R227 R228 R231 R232 R235 R236 T2 T5 TP11 TP12; alternate parts U1 -> ADC32RF77ANH, U1 -> ADC32RF77ANH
